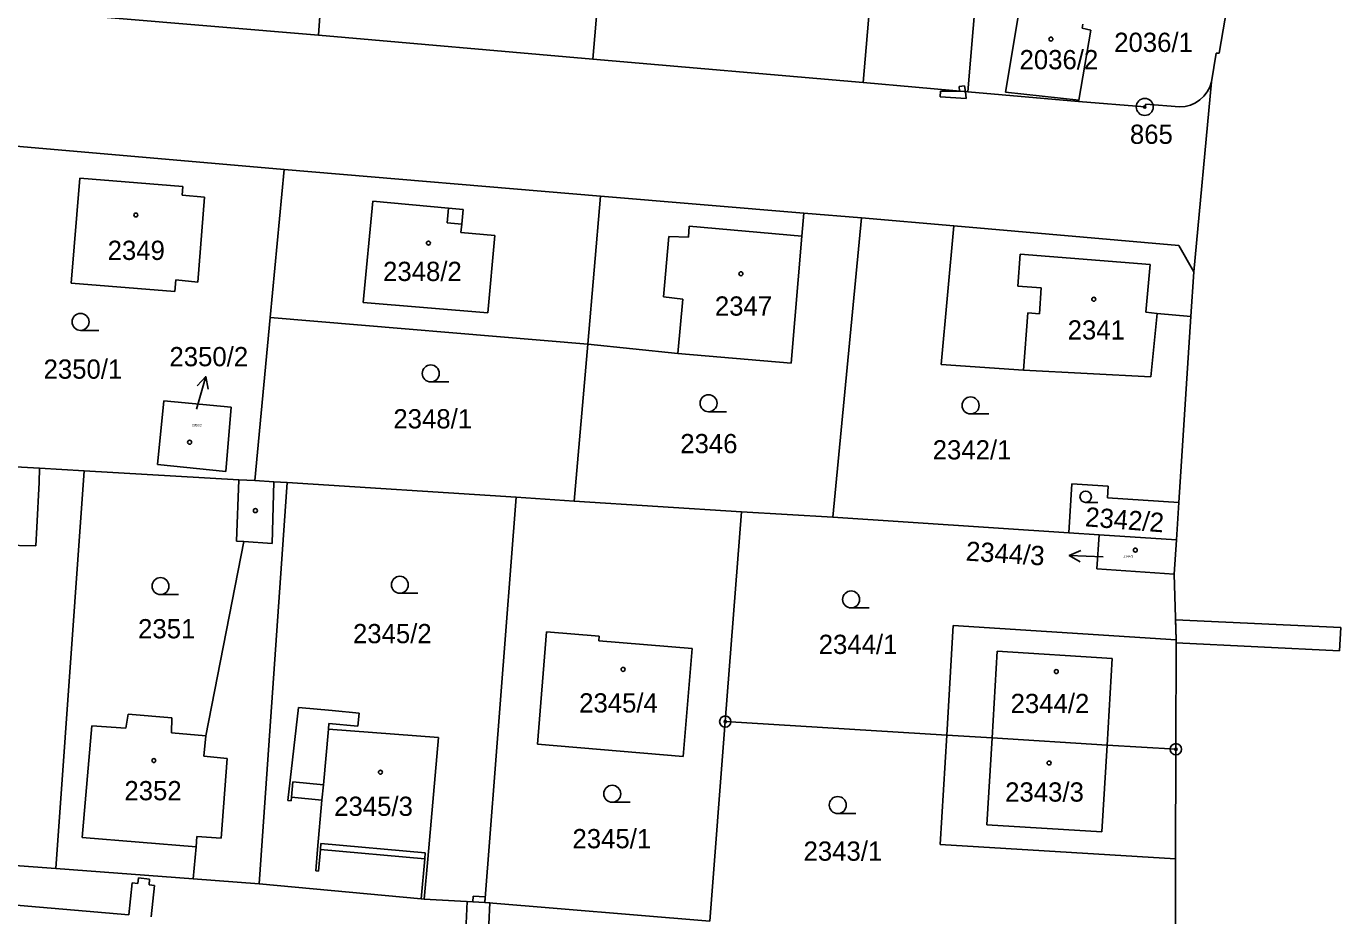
# Model space of a CAD drawing. Extents: x -755819 to -753140, y -1169796 to -1166000.
# Drawn here: x -755476.4 to -755360.3, y -1168132.3 to -1168053.8 of the extents above; entities that cross this region are included whole.
import ezdxf

# ---------------------------------------------------------------- set-up
doc = ezdxf.new("R2010")
doc.units = 0
for name, color, linetype in [('Vrstva 1', 7, 'Continuous'), ('Vrstva 16', 7, 'Continuous'), ('Vrstva 17', 7, 'Continuous'), ('Vrstva 18', 7, 'Continuous'), ('Vrstva 19', 7, 'Continuous'), ('Vrstva 24', 7, 'Continuous'), ('Vrstva 25', 7, 'Continuous'), ('Vrstva 27', 7, 'Continuous'), ('Vrstva 4', 7, 'Continuous')]:
    doc.layers.add(name, color=color, linetype=linetype)

msp = doc.modelspace()

# ---------------------------------------------------------------- linework, layer by layer
at = {"layer": 'Vrstva 1'}
for p, q in [((-755423.38, -1168022.54), (-755426.37, -1168056.66)), ((-755450.61, -1168054.55), (-755448.74, -1168028.36)), ((-755400.33, -1168033.58), (-755402.48, -1168058.74)), ((-755391.69, -1168040.86), (-755393.26, -1168059.55)), ((-755371.06, -1168056.13), (-755370.04, -1168050.36)), ((-755478.43, -1168052.22), (-755450.61, -1168054.55)), ((-755388.77, -1168052.72), (-755389.92, -1168059.58)), ((-755383.08, -1168053.59), (-755383.14, -1168053.94)), ((-755383.14, -1168053.94), (-755382.39, -1168054.11)), ((-755426.37, -1168056.66), (-755450.61, -1168054.55)), ((-755382.39, -1168054.11), (-755383.44, -1168060.28)), ((-755371.32, -1168056.14), (-755371.71, -1168058.67)), ((-755371.32, -1168056.14), (-755371.06, -1168056.13)), ((-755402.48, -1168058.74), (-755426.37, -1168056.66)), ((-755373.29, -1168075.45), (-755371.71, -1168058.67)), ((-755402.48, -1168058.74), (-755393.26, -1168059.55)), ((-755393.26, -1168059.55), (-755383.46, -1168060.4)), ((-755389.92, -1168059.58), (-755383.44, -1168060.28)), ((-755383.44, -1168060.28), (-755383.46, -1168060.4)), ((-755377.62, -1168060.89), (-755383.46, -1168060.4)), ((-755377.52, -1168060.65), (-755377.62, -1168060.89)), ((-755377.52, -1168060.65), (-755374.54, -1168060.89)), ((-755453.63, -1168066.4), (-755481.35, -1168064.02)), ((-755453.63, -1168066.4), (-755454.87, -1168079.48)), ((-755453.63, -1168066.4), (-755425.68, -1168068.78)), ((-755472.45, -1168076.46), (-755471.7, -1168067.19)), ((-755471.7, -1168067.19), (-755462.58, -1168067.92)), ((-755462.58, -1168067.92), (-755462.64, -1168068.69)), ((-755462.64, -1168068.69), (-755460.68, -1168068.87)), ((-755460.68, -1168068.87), (-755461.27, -1168076.36)), ((-755425.68, -1168068.78), (-755426.81, -1168081.83)), ((-755425.68, -1168068.78), (-755407.74, -1168070.27)), ((-755407.91, -1168072.3), (-755407.74, -1168070.27)), ((-755407.74, -1168070.27), (-755402.64, -1168070.69)), ((-755402.64, -1168070.69), (-755405.17, -1168097.12)), ((-755402.64, -1168070.69), (-755394.49, -1168071.4)), ((-755394.49, -1168071.4), (-755395.61, -1168083.64)), ((-755394.49, -1168071.4), (-755374.62, -1168073.13)), ((-755408.85, -1168083.51), (-755407.91, -1168072.3)), ((-755374.62, -1168073.13), (-755373.29, -1168075.45)), ((-755373.54, -1168079.39), (-755373.29, -1168075.45)), ((-755463.29, -1168077.2), (-755472.45, -1168076.46)), ((-755463.21, -1168076.15), (-755463.29, -1168077.2)), ((-755461.27, -1168076.36), (-755463.21, -1168076.15)), ((-755454.87, -1168079.48), (-755456.23, -1168093.88)), ((-755454.87, -1168079.48), (-755426.81, -1168081.83)), ((-755377.07, -1168084.72), (-755376.53, -1168079.12)), ((-755376.53, -1168079.12), (-755373.54, -1168079.39)), ((-755373.54, -1168079.39), (-755374.6, -1168095.82)), ((-755426.81, -1168081.83), (-755428.01, -1168095.69)), ((-755426.81, -1168081.83), (-755418.85, -1168082.65)), ((-755418.85, -1168082.65), (-755408.85, -1168083.51)), ((-755395.61, -1168083.64), (-755388.34, -1168084.13)), ((-755388.34, -1168084.13), (-755377.07, -1168084.72)), ((-755464.83, -1168092.48), (-755464.27, -1168086.84)), ((-755464.27, -1168086.84), (-755458.33, -1168087.39)), ((-755458.33, -1168087.39), (-755458.78, -1168093.07)), ((-755475.26, -1168092.79), (-755482.03, -1168092.4)), ((-755475.28, -1168094.05), (-755475.26, -1168092.79)), ((-755471.3, -1168093.02), (-755475.26, -1168092.79)), ((-755471.3, -1168093.02), (-755473.81, -1168128.15)), ((-755471.3, -1168093.02), (-755457.65, -1168093.82)), ((-755458.78, -1168093.07), (-755464.83, -1168092.48)), ((-755475.48, -1168097.99), (-755475.28, -1168094.05)), ((-755457.84, -1168099.23), (-755457.65, -1168093.82)), ((-755457.65, -1168093.82), (-755456.23, -1168093.88)), ((-755456.23, -1168093.88), (-755454.54, -1168094)), ((-755453.37, -1168094.06), (-755455.85, -1168129.51)), ((-755454.54, -1168094), (-755453.37, -1168094.06)), ((-755433.14, -1168095.35), (-755453.37, -1168094.06)), ((-755384.05, -1168094.18), (-755384.34, -1168098.5)), ((-755380.86, -1168094.39), (-755384.05, -1168094.18)), ((-755380.92, -1168095.4), (-755380.86, -1168094.39)), ((-755433.14, -1168095.35), (-755435.92, -1168131.15)), ((-755428.01, -1168095.69), (-755433.14, -1168095.35)), ((-755413.23, -1168096.65), (-755428.01, -1168095.69)), ((-755374.6, -1168095.82), (-755380.92, -1168095.4)), ((-755374.82, -1168099.12), (-755374.6, -1168095.82)), ((-755414.67, -1168115.17), (-755413.23, -1168096.65)), ((-755405.17, -1168097.12), (-755413.23, -1168096.65)), ((-755475.57, -1168099.65), (-755475.48, -1168097.99)), ((-755405.17, -1168097.12), (-755384.34, -1168098.5)), ((-755460.57, -1168116.43), (-755457.21, -1168099.27)), ((-755457.84, -1168099.23), (-755457.21, -1168099.27)), ((-755384.34, -1168098.5), (-755381.66, -1168098.67)), ((-755381.66, -1168098.67), (-755381.86, -1168101.67)), ((-755381.66, -1168098.67), (-755374.82, -1168099.12)), ((-755375.01, -1168102.15), (-755374.82, -1168099.12)), ((-755478.49, -1168099.58), (-755475.57, -1168099.65)), ((-755381.86, -1168101.67), (-755375.01, -1168102.15)), ((-755375.01, -1168102.15), (-755374.84, -1168107.95)), ((-755431.26, -1168117.17), (-755430.46, -1168107.25)), ((-755430.46, -1168107.25), (-755425.81, -1168107.63)), ((-755394.54, -1168106.69), (-755395.1, -1168116.37)), ((-755394.54, -1168106.69), (-755374.84, -1168107.95)), ((-755425.81, -1168107.63), (-755425.83, -1168108.05)), ((-755425.83, -1168108.05), (-755417.59, -1168108.73)), ((-755374.84, -1168107.95), (-755374.87, -1168117.62)), ((-755417.59, -1168108.73), (-755418.38, -1168118.24)), ((-755452.37, -1168113.93), (-755453.3, -1168122.14)), ((-755449.39, -1168114.2), (-755452.37, -1168113.93)), ((-755447, -1168114.43), (-755449.39, -1168114.2)), ((-755471.49, -1168125.42), (-755470.62, -1168115.55)), ((-755470.62, -1168115.55), (-755467.61, -1168115.76)), ((-755467.61, -1168115.76), (-755467.41, -1168114.53)), ((-755467.41, -1168114.53), (-755463.56, -1168114.85)), ((-755463.56, -1168114.85), (-755463.6, -1168116.17)), ((-755449.73, -1168115.83), (-755449.69, -1168115.33)), ((-755449.69, -1168115.33), (-755447.12, -1168115.57)), ((-755447.12, -1168115.57), (-755447, -1168114.43)), ((-755416.04, -1168132.79), (-755414.67, -1168115.17)), ((-755414.67, -1168115.17), (-755395.1, -1168116.37)), ((-755463.6, -1168116.17), (-755460.57, -1168116.43)), ((-755439.99, -1168116.59), (-755449.73, -1168115.83)), ((-755440.95, -1168127.33), (-755439.99, -1168116.59)), ((-755395.1, -1168116.37), (-755395.7, -1168126.03)), ((-755395.1, -1168116.37), (-755391.11, -1168116.61)), ((-755391.11, -1168116.61), (-755380.95, -1168117.25)), ((-755418.38, -1168118.24), (-755431.26, -1168117.17)), ((-755380.95, -1168117.25), (-755374.87, -1168117.62)), ((-755374.87, -1168117.62), (-755374.9, -1168127.3)), ((-755453, -1168121.86), (-755452.88, -1168120.5)), ((-755452.88, -1168120.5), (-755450.17, -1168120.75)), ((-755450.17, -1168120.75), (-755450.3, -1168122.1)), ((-755453.3, -1168122.14), (-755453.03, -1168122.17)), ((-755453.03, -1168122.17), (-755453, -1168121.86)), ((-755450.3, -1168122.1), (-755450.69, -1168126.46)), ((-755461.42, -1168126.24), (-755471.49, -1168125.42)), ((-755395.7, -1168126.03), (-755374.9, -1168127.3)), ((-755496.37, -1168126.5), (-755473.81, -1168128.15)), ((-755461.42, -1168126.24), (-755461.67, -1168129.07)), ((-755450.69, -1168126.46), (-755450.85, -1168128.35)), ((-755450.6, -1168128.38), (-755450.44, -1168126.48)), ((-755450.44, -1168126.48), (-755441.22, -1168127.3)), ((-755473.81, -1168128.15), (-755461.67, -1168129.07)), ((-755450.85, -1168128.35), (-755450.6, -1168128.38)), ((-755441.22, -1168127.3), (-755441.53, -1168130.83)), ((-755441.26, -1168130.86), (-755440.95, -1168127.33)), ((-755374.9, -1168127.3), (-755374.91, -1168133.22)), ((-755461.67, -1168129.07), (-755455.85, -1168129.51)), ((-755441.53, -1168130.83), (-755455.85, -1168129.51)), ((-755441.26, -1168130.86), (-755441.53, -1168130.83)), ((-755435.92, -1168131.15), (-755441.26, -1168130.86)), ((-755416.04, -1168132.79), (-755435.92, -1168131.15))]:
    msp.add_line(p, q, dxfattribs=at)
msp.add_arc((-755374.57, -1168057.94), 2.95, 270.524, 345.701, dxfattribs=at)
at = {"layer": 'Vrstva 16'}
for p, q in [((-755460.57, -1168084.7), (-755461.38, -1168087.59)), ((-755384.29, -1168100.51), (-755381.29, -1168100.62))]:
    msp.add_line(p, q, dxfattribs=at)
for points in [[(-755461.32, -1168085.53), (-755460.57, -1168084.7), (-755460.36, -1168085.8)], [(-755383.31, -1168101.05), (-755384.29, -1168100.51), (-755383.27, -1168100.05)]]:
    msp.add_lwpolyline(points, dxfattribs=at)
at = {"layer": 'Vrstva 24'}
for centre, radius in [((-755377.62, -1168060.89), 0.75), ((-755377.62, -1168060.89), 0.1), ((-755414.67, -1168115.17), 0.5), ((-755414.67, -1168115.17), 0.1), ((-755374.87, -1168117.62), 0.5), ((-755374.87, -1168117.62), 0.1)]:
    msp.add_circle(centre, radius, dxfattribs=at)
at = {"layer": 'Vrstva 25'}
for p, q in [((-755471.62, -1168080.62), (-755470.02, -1168080.62)), ((-755440.69, -1168085.17), (-755439.09, -1168085.17)), ((-755416.15, -1168087.81), (-755414.55, -1168087.81)), ((-755393, -1168088), (-755391.4, -1168088)), ((-755382.84, -1168095.81), (-755381.77, -1168095.81)), ((-755464.56, -1168103.96), (-755462.96, -1168103.96)), ((-755443.42, -1168103.84), (-755441.82, -1168103.84)), ((-755403.56, -1168105.13), (-755401.96, -1168105.13)), ((-755424.66, -1168122.3), (-755423.06, -1168122.3)), ((-755404.74, -1168123.29), (-755403.14, -1168123.29))]:
    msp.add_line(p, q, dxfattribs=at)
for centre, radius in [((-755385.91, -1168054.9), 0.175), ((-755466.74, -1168070.43), 0.175), ((-755440.89, -1168072.91), 0.175), ((-755413.29, -1168075.62), 0.175), ((-755382.12, -1168077.87), 0.175), ((-755471.62, -1168079.87), 0.75), ((-755440.69, -1168084.42), 0.75), ((-755416.15, -1168087.06), 0.75), ((-755393, -1168087.25), 0.75), ((-755461.99, -1168090.5), 0.175), ((-755382.84, -1168095.31), 0.503), ((-755456.18, -1168096.54), 0.175), ((-755378.45, -1168100.03), 0.175), ((-755464.56, -1168103.21), 0.75), ((-755443.42, -1168103.09), 0.75), ((-755403.56, -1168104.38), 0.75), ((-755423.7, -1168110.56), 0.175), ((-755385.43, -1168110.75), 0.175), ((-755465.15, -1168118.61), 0.175), ((-755386.07, -1168118.83), 0.175), ((-755445.13, -1168119.64), 0.175), ((-755424.66, -1168121.55), 0.75), ((-755404.74, -1168122.54), 0.75)]:
    msp.add_circle(centre, radius, dxfattribs=at)
at = {"layer": 'Vrstva 27'}
for p, q in [((-755395.69, -1168059.99), (-755395.66, -1168059.49)), ((-755395.66, -1168059.49), (-755393.97, -1168059.49)), ((-755394.02, -1168059.08), (-755393.53, -1168059.02)), ((-755393.97, -1168059.49), (-755394.02, -1168059.08)), ((-755393.46, -1168059.53), (-755393.97, -1168059.49)), ((-755393.97, -1168059.49), (-755393.46, -1168059.53)), ((-755393.53, -1168059.02), (-755393.46, -1168059.53)), ((-755393.46, -1168059.53), (-755393.38, -1168060.13)), ((-755393.38, -1168060.13), (-755395.69, -1168059.99)), ((-755374.89, -1168106.19), (-755360.31, -1168106.87)), ((-755374.84, -1168107.95), (-755374.89, -1168106.19)), ((-755360.31, -1168106.87), (-755360.41, -1168108.92)), ((-755374.84, -1168108.23), (-755374.84, -1168107.95)), ((-755360.41, -1168108.92), (-755374.84, -1168108.23)), ((-755467.37, -1168132.23), (-755467.06, -1168129.42)), ((-755467.06, -1168129.42), (-755466.57, -1168129.48)), ((-755466.57, -1168129.48), (-755466.51, -1168128.98)), ((-755466.51, -1168128.98), (-755465.52, -1168129.09)), ((-755465.52, -1168129.09), (-755465.57, -1168129.58)), ((-755465.57, -1168129.58), (-755465.08, -1168129.64)), ((-755465.08, -1168129.64), (-755465.38, -1168132.4)), ((-755436.98, -1168131.09), (-755436.95, -1168130.59)), ((-755436.95, -1168130.59), (-755435.88, -1168130.65)), ((-755435.88, -1168130.65), (-755435.92, -1168131.15)), ((-755482.58, -1168130.92), (-755467.37, -1168132.23)), ((-755437.65, -1168134.97), (-755437.47, -1168131.07)), ((-755437.47, -1168131.07), (-755436.98, -1168131.09)), ((-755436.98, -1168131.09), (-755435.92, -1168131.15)), ((-755435.92, -1168131.15), (-755436.98, -1168131.09)), ((-755435.92, -1168131.15), (-755435.48, -1168131.19)), ((-755435.48, -1168131.19), (-755435.66, -1168135.13))]:
    msp.add_line(p, q, dxfattribs=at)
at = {"layer": 'Vrstva 4'}
for p, q in [((-755446.66, -1168078.16), (-755445.8, -1168069.2)), ((-755445.8, -1168069.2), (-755439.13, -1168069.83)), ((-755439.13, -1168069.83), (-755439.25, -1168071.12)), ((-755439.13, -1168069.83), (-755437.83, -1168069.95)), ((-755437.83, -1168069.95), (-755437.95, -1168071.25)), ((-755439.25, -1168071.12), (-755437.95, -1168071.25)), ((-755437.95, -1168071.25), (-755438.02, -1168071.97)), ((-755417.85, -1168071.42), (-755417.93, -1168072.4)), ((-755407.91, -1168072.3), (-755417.85, -1168071.42)), ((-755438.02, -1168071.97), (-755435.04, -1168072.24)), ((-755435.04, -1168072.24), (-755435.64, -1168079.08)), ((-755419.67, -1168072.34), (-755420.13, -1168077.67)), ((-755417.93, -1168072.4), (-755419.67, -1168072.34)), ((-755388.63, -1168073.89), (-755388.82, -1168076.72)), ((-755388.63, -1168073.89), (-755377.14, -1168074.79)), ((-755377.14, -1168074.79), (-755377.53, -1168079.02)), ((-755388.82, -1168076.72), (-755386.76, -1168076.87)), ((-755386.76, -1168076.87), (-755386.93, -1168079.16)), ((-755435.64, -1168079.08), (-755446.66, -1168078.16)), ((-755420.13, -1168077.67), (-755418.42, -1168077.87)), ((-755418.42, -1168077.87), (-755418.85, -1168082.65)), ((-755387.95, -1168079.08), (-755388.34, -1168084.13)), ((-755386.93, -1168079.16), (-755387.95, -1168079.08)), ((-755377.53, -1168079.02), (-755376.53, -1168079.12)), ((-755454.54, -1168094), (-755454.7, -1168099.45)), ((-755454.7, -1168099.45), (-755457.21, -1168099.27)), ((-755391.11, -1168116.61), (-755390.65, -1168108.94)), ((-755390.65, -1168108.94), (-755380.5, -1168109.59)), ((-755380.5, -1168109.59), (-755380.95, -1168117.25)), ((-755460.57, -1168116.43), (-755460.72, -1168118.23)), ((-755449.73, -1168115.83), (-755450.17, -1168120.75)), ((-755391.56, -1168124.28), (-755391.11, -1168116.61)), ((-755380.95, -1168117.25), (-755381.41, -1168124.9)), ((-755460.72, -1168118.23), (-755458.68, -1168118.43)), ((-755458.68, -1168118.43), (-755459.2, -1168125.46)), ((-755453, -1168121.86), (-755450.3, -1168122.1)), ((-755381.41, -1168124.9), (-755391.56, -1168124.28)), ((-755461.34, -1168125.33), (-755461.42, -1168126.24)), ((-755459.2, -1168125.46), (-755461.34, -1168125.33)), ((-755450.44, -1168126.48), (-755450.39, -1168125.93)), ((-755450.39, -1168125.93), (-755441.17, -1168126.76)), ((-755441.17, -1168126.76), (-755441.22, -1168127.3))]:
    msp.add_line(p, q, dxfattribs=at)

# ---------------------------------------------------------------- texts
at = {"layer": 'Vrstva 16'}
msp.add_text('2350/2', height=1.7, dxfattribs=at).set_placement((-755463.77, -1168083.79))
msp.add_text('2344/3', height=1.7, rotation=356.3797, dxfattribs=at).set_placement((-755393.46, -1168100.95))
at = {"layer": 'Vrstva 17'}
msp.add_text('865', height=1.7, dxfattribs=at).set_placement((-755378.93, -1168064.15))
at = {"layer": 'Vrstva 18'}
for s, p in [('2350/1', (-755474.89, -1168084.89)), ('2348/1', (-755443.99, -1168089.28)), ('2346', (-755418.65, -1168091.47)), ('2342/1', (-755396.35, -1168092.02)), ('2351', (-755466.54, -1168107.82)), ('2345/2', (-755447.56, -1168108.25)), ('2344/1', (-755406.42, -1168109.2)), ('2345/1', (-755428.17, -1168126.36)), ('2343/1', (-755407.76, -1168127.46))]:
    msp.add_text(s, height=1.7, dxfattribs=at).set_placement(p)
msp.add_text('2342/2', height=1.7, rotation=355.5203, dxfattribs=at).set_placement((-755382.93, -1168097.92))
at = {"layer": 'Vrstva 19'}
for s, height, p in [('2036/1', 1.7, (-755380.32, -1168056.03)), ('2036/2', 1.7, (-755388.68, -1168057.56)), ('2349', 1.7, (-755469.23, -1168074.4)), ('2348/2', 1.7, (-755444.9, -1168076.26)), ('2347', 1.7, (-755415.59, -1168079.32)), ('2341', 1.7, (-755384.43, -1168081.43)), ('2350/2', 0.2, (-755461.77, -1168089.09)), ('2344/3', 0.2, (-755379.49, -1168100.68)), ('2345/4', 1.7, (-755427.58, -1168114.37)), ('2344/2', 1.7, (-755389.47, -1168114.42)), ('2352', 1.7, (-755467.75, -1168122.12)), ('2343/3', 1.7, (-755389.95, -1168122.24)), ('2345/3', 1.7, (-755449.22, -1168123.5))]:
    msp.add_text(s, height=height, dxfattribs=at).set_placement(p)

doc.saveas('drawing.dxf')
